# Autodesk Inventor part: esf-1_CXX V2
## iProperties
Created: 2009-11
Part Number: esf-1_CXX V2
Document SubType Name: Modeling
Designer: Oliver Liedtke
Density: 1 g/cm^3
Author: Oliver Liedtke
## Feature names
1. Gehäusekontur [Extrusion]
2. Befestigungsbohrungen [Hole]
3. Rundung2 [Fillet]
4. Bohrung USW [Extrusion]
5. Stufe Sender USW [Extrusion]
6. Stufe Empf. USW [Extrusion]
7. Rundung3 [Fillet]
8. Rundung8 [Fillet]
9. V2: Schmutzrinne Sender #1 [Extrusion]
10. V2: Schmutzrinne Sender #2 [Extrusion]
11. V2: Rundung4 [Fillet]
12. Ex Empf. [Extrusion]
13. Ex Sender [Extrusion]
14. Marke rechts [Extrusion]
15. Marke links [Extrusion]
16. M12 [Extrusion]
17. Extrusion37
18. Fase3 [Chamfer]
19. Extrusion38
20. Extrusion39
21. Extrusion40
22. Rundung9 [Fillet]
23. Extrusion41
24. Extrusion42
25. Rundung10 [Fillet]
26. mic-Logo [Extrusion]
27. mic-Logo Folie [Extrusion]
